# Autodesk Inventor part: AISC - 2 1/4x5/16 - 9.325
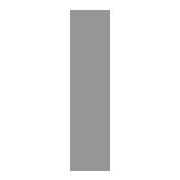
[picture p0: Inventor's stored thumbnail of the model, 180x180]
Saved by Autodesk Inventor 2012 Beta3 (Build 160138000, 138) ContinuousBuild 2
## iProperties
_CCFamilyMember: 149
_CCFamilyDisplayName: ANSI AISC (Rectangular) - Flat Bar Steel
_FrameMemberDoc: Frame Member File
_Version: 15.0.0
_GetPNFromCC: 1
Created: 2010-11
Part Number: AISC - 2 1/4x5/16 - 9.325
Material: Steel, Mild
Description: Flat Bar Steel
Document SubType Name: Modeling
Standard: ANSI
Designer: Beta-8540w
Standards Organization: ANSI
Language: en-US
Size Designation: 2 1/4x5/16
Categories: <MemberInstance><Categories><Category DisplayName="Structural Shapes" InternalName="089c4875-fa83-4c05-b084-43b9cc11f5ed" Mnemonic="GRDR"><CategoryParameter Dis
Stock Number: 2 1/4x5/16
Density: 7.86 g/cm^3
IsCustomPart: 1
G_L: 9.325 in
G_W: 0.313 in
G_H: 2.250 in
Author: Beta-8540w
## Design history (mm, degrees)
node "Start plane"
node "End plane"
node "Driven Length"
  sketch "Sketch3"
    geometry: L1 (0, 0)-(10, 0) reference
    constraints: 2 end point, 1 horizontal
  workplane "Work Plane3"
  sketch "Sketch4"
    geometry: L1 (-2, 0)-(12, 0) reference; L2 (-40.005, 236.864)-(40.005, 236.864) reference
    dimensions: "d9" = 236.86413 distance between parallel lines of L1 L2 (derived)
sketch "Sweep Path"
  geometry: L1 through (-25.4, 40.279) direction (1, 0); L2 through (-112.121, 127) direction (1, 0); 9 other entities
  constraints: 10 horizontal
node "Orientation Work Plane"
feature "Body" dims "d10" = 0
body "Solid1"
sketch "Sketch"
  geometry: L1 (3.969, -28.575)-(-3.969, -28.575); L2 (-3.969, -28.575)-(-3.969, 28.575); L3 (-3.969, 28.575)-(3.969, 28.575); L4 (3.969, 28.575)-(3.969, -28.575); L5 (-6, 0)-(8, 0); L6 (0, -30)-(0, 40); L7 (0, 54)-(0, -44); L8 (-9.2, 0)-(13.2, 0)
  constraints: 16 end point, 2 collinear, 2 parallel, 1 horizontal, 1 perpendicular
  dimensions: "d0" = 57.15 distance between parallel lines of L3 L1 (= G_W); "d1" = 7.9375 distance between parallel lines of L4 L2 (= G_H); "d4" = 3.96875 distance between parallel lines of L6 L4 (= 0.5 x d1); "d5" = 28.575 distance between parallel lines of L5 L3 (= 0.5 x d0)
other parameters: "G_W" = 57.15 [user parameter; used in 1 equation term], "G_H" = 7.9375 [user parameter; used in 1 equation term], "G_L" = 236.86413 (= d9) [user parameter], "G_OFFSET_START" = 0 [user parameter; used in 1 equation term], "G_OFFSET_END" = 0 [user parameter; used in 1 equation term], "d6" = 0 (computed from G_OFFSET_START), "d7" = 236.86413 (= G_OFFSET_END + B_L), "B_L" = 236.86413 [user parameter; used in 1 equation term], "d8" = 90 deg
